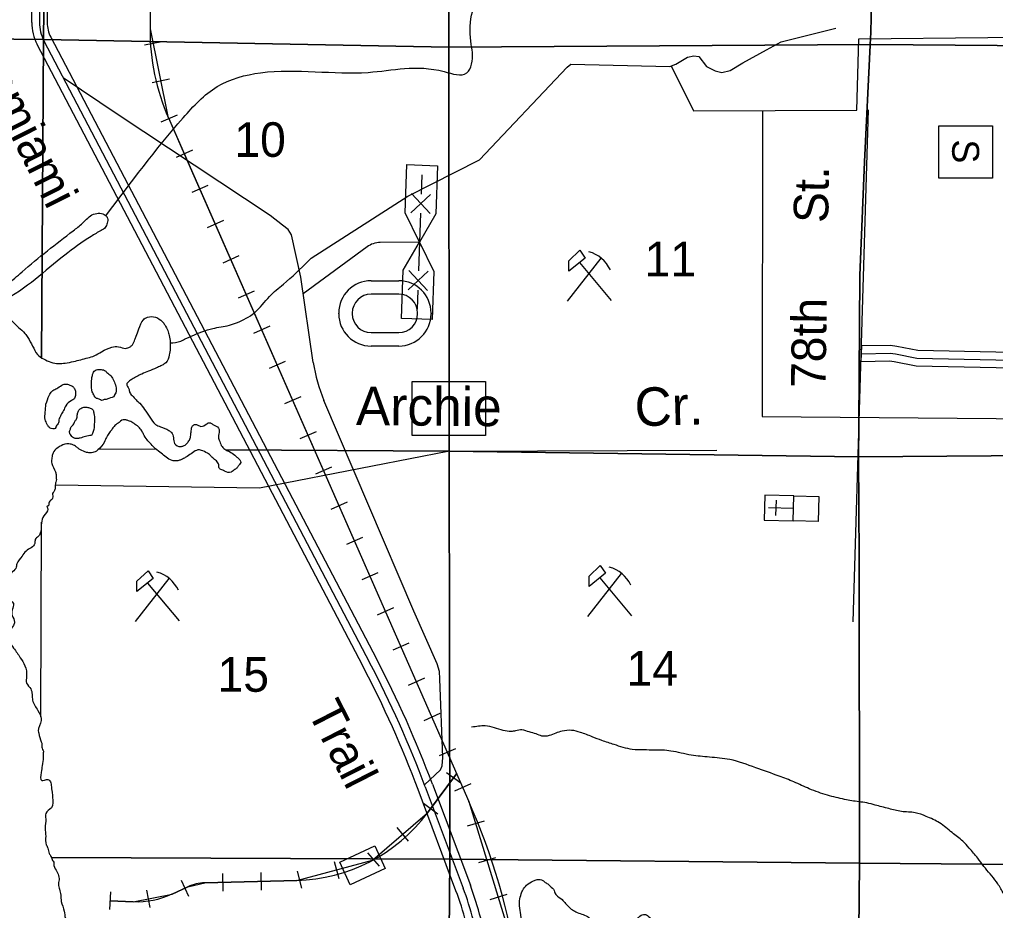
# Model space of a CAD drawing. Extents: x 380424 to 701066, y 1117407 to 1412949.
# Drawn here: x 526006 to 538699, y 1282967 to 1294552 of the extents above; entities that cross this region are included whole.
import ezdxf

# ---------------------------------------------------------------- set-up
doc = ezdxf.new("R2010")
doc.units = 0
for name, color, linetype in [('Cities Incorporated Area', 7, 'Continuous'), ('Culture', 7, 'Continuous'), ('Islands', 7, 'Continuous'), ('Lakes and Ponds Text', 7, 'Continuous'), ('Local Roads Divided Highway Outline and Fill', 7, 'Continuous'), ('Local Roads Paved', 7, 'Continuous'), ('Local Roads Related Cells', 7, 'Continuous'), ('Local Roads Related Text', 7, 'Continuous'), ('Masks for Text', 7, 'Continuous'), ('Narrow Canals', 7, 'Continuous'), ('Narrow River Creek and Branch and Slough', 7, 'Continuous'), ('Railroad Stations', 7, 'Continuous'), ('Railroads', 7, 'Continuous'), ('Section Lines', 7, 'Continuous'), ('Section Numbers', 7, 'Continuous'), ('US Highways Related Text', 7, 'Continuous'), ('US Route Divided Highway Outline and Fill', 7, 'Continuous'), ('US Routes Highway Center Lines', 7, 'Continuous'), ('Wide Rivers and Canals', 7, 'Continuous')]:
    doc.layers.add(name, color=color, linetype=linetype)

msp = doc.modelspace()

# ---------------------------------------------------------------- linework, layer by layer
at = {"layer": 'Cities Incorporated Area'}
for points in [[(523814, 1294042), (523870, 1293952), (523903, 1293762), (523903, 1293715), (524050, 1293710), (524183, 1293592), (524325, 1293478), (524339, 1293379), (524358, 1293152), (524495, 1293076), (524528, 1293000), (524618, 1292877), (524656, 1292825), (524708, 1292782), (524846, 1292750), (524883, 1292670), (524957, 1292539), (525068, 1292391), (525142, 1292327), (525216, 1292196), (525247, 1292111), (525290, 1292006), (525353, 1291905), (525453, 1291810), (525553, 1291736), (525627, 1291620), (525664, 1291531), (525659, 1291404), (525627, 1291219), (525590, 1291082), (525538, 1290966), (525538, 1290929), (525574, 1290929), (525648, 1290966), (525717, 1291003), (525849, 1291103), (526039, 1291272), (526704, 1291805), (526825, 1291905), (526968, 1292021), (527052, 1292032), (527121, 1292006), (527152, 1291969), (527147, 1291905), (527121, 1291847), (527068, 1291810), (526936, 1291731), (526593, 1291488), (525775, 1290882), (525675, 1290792), (525685, 1290734), (525717, 1290713), (525749, 1290697), (525786, 1290686), (525828, 1290681), (525849, 1290676), (525896, 1290644), (525933, 1290607), (525991, 1290549), (526076, 1290470), (526113, 1290417), (526176, 1290306), (526239, 1290196), (526319, 1290138), (526414, 1290095), (526514, 1290079), (526598, 1290085), (526709, 1290106), (526894, 1290153), (526978, 1290180), (527073, 1290233), (527205, 1290291), (527295, 1290296), (527384, 1290275), (527443, 1290296), (527474, 1290322), (527506, 1290391), (527522, 1290433), (527559, 1290528), (527617, 1290649), (527669, 1290681), (527775, 1290681), (527865, 1290623), (527896, 1290581), (527933, 1290507), (527954, 1290444), (527965, 1290359), (527965, 1290275), (527954, 1290190), (527907, 1290090), (527881, 1290069), (527844, 1290048), (527786, 1290021), (527685, 1289979), (527596, 1289942), (527469, 1289874), (527427, 1289847)], [(527427, 1289847), (527400, 1289810), (527427, 1289752), (527437, 1289705), (527469, 1289663), (527522, 1289605), (527569, 1289562), (527632, 1289483), (527701, 1289383), (527775, 1289288), (527838, 1289256), (527949, 1289209), (527981, 1289182), (528007, 1289114), (528023, 1289040), (528102, 1288998), (528123, 1289003), (528139, 1289008), (528176, 1289035), (528208, 1289072), (528229, 1289119), (528234, 1289172), (528239, 1289204), (528255, 1289267), (528292, 1289288), (528324, 1289277), (528366, 1289262), (528440, 1289293), (528482, 1289309), (528493, 1289304), (528530, 1289283), (528593, 1289240), (528603, 1289204), (528593, 1289124), (528609, 1289066), (528640, 1288998), (528688, 1288955), (528735, 1288934), (528804, 1288887), (528841, 1288855), (528883, 1288792), (528867, 1288766), (528857, 1288755), (528830, 1288718), (528815, 1288707), (528772, 1288676), (528757, 1288665), (528672, 1288681), (528625, 1288702), (528598, 1288729), (528598, 1288755), (528593, 1288776), (528556, 1288824), (528508, 1288861), (528477, 1288897), (528450, 1288913), (528371, 1288950), (528324, 1288955), (528255, 1288919), (528187, 1288871), (528150, 1288850), (528097, 1288824), (528055, 1288813), (528018, 1288813), (527991, 1288818), (527912, 1288861), (527849, 1288913), (527775, 1288971), (527717, 1289029), (527664, 1289087), (527617, 1289161), (527596, 1289204), (527495, 1289298), (527437, 1289330), (527406, 1289341), (527390, 1289346), (527369, 1289346), (527353, 1289346), (527321, 1289330), (527316, 1289325), (527258, 1289283), (527237, 1289262), (527205, 1289219), (527136, 1289119), (527110, 1289061), (527026, 1288955), (527005, 1288940), (526941, 1288919), (526878, 1288924), (526836, 1288940), (526767, 1288977), (526735, 1289003), (526677, 1289029), (526619, 1289035), (526524, 1288998), (526450, 1288934), (526435, 1288897)], [(526435, 1288897), (526424, 1288839), (526424, 1288781), (526473, 1288671), (526481, 1288625), (526481, 1288598), (526485, 1288571), (526477, 1288537), (526473, 1288514), (526469, 1288483), (526469, 1288449), (526450, 1288411), (526436, 1288391), (526436, 1288376), (526429, 1288316), (526391, 1288278), (526376, 1288226), (526361, 1288218), (526369, 1288204), (526339, 1288122), (526294, 1288031), (526249, 1287829), (526211, 1287791), (526204, 1287738), (526091, 1287641), (526038, 1287573), (525971, 1287476), (525956, 1287415), (525902, 1287357), (525881, 1287304), (525858, 1287251), (525843, 1287244), (525888, 1287139), (525851, 1287041), (525926, 1286958), (525911, 1286876), (525911, 1286801), (525941, 1286718), (525926, 1286673), (525844, 1286539), (525928, 1286380), (526016, 1286254), (526076, 1286149), (526098, 1286013), (526098, 1285923), (526151, 1285848), (526176, 1285700), (526245, 1285568), (526287, 1285436), (526249, 1285301), (526256, 1285271), (526287, 1285161), (526294, 1285143), (526298, 1285092), (526306, 1285060), (526316, 1285038), (526314, 1285018), (526313, 1285000), (526313, 1284960), (526301, 1284850), (526286, 1284760), (526294, 1284655), (526376, 1284670), (526414, 1284625), (526421, 1284557), (526429, 1284512), (526436, 1284437), (526421, 1284302), (526346, 1284227), (526346, 1284159), (526339, 1284039), (526346, 1283934), (526354, 1283821), (526376, 1283776), (526391, 1283708), (526414, 1283671), (526436, 1283618), (526451, 1283595), (526451, 1283573), (526481, 1283490), (526519, 1283348), (526511, 1283310), (526526, 1283242), (526541, 1283167), (526549, 1283085), (526587, 1282957), (526602, 1282867), (526632, 1282792), (526656, 1282702), (526688, 1282591), (526714, 1282539), (526762, 1282401), (526799, 1282333), (526878, 1282217), (526941, 1282159), (527084, 1282021), (527115, 1281937)]]:
    msp.add_spline(points, degree=3, dxfattribs=at)
at = {"layer": 'Culture'}
for p, q in [((533132, 1290890), (533569, 1291450)), ((533288, 1291391), (533702, 1290899)), ((530578, 1291156), (530938, 1291156)), ((530938, 1290981), (530578, 1290981)), ((530158, 1290726), (530158, 1290736)), ((530333, 1290736), (530333, 1290726)), ((531183, 1290726), (531183, 1290736)), ((531358, 1290736), (531358, 1290726)), ((530578, 1290481), (530938, 1290481)), ((530938, 1290306), (530578, 1290306)), ((535701, 1288368), (535692, 1288043)), ((536075, 1288358), (535701, 1288368)), ((535843, 1288102), (535849, 1288302)), ((536066, 1288033), (536075, 1288358)), ((536071, 1288195), (535746, 1288204)), ((535692, 1288043), (536066, 1288033)), ((527514, 1286724), (527951, 1287284)), ((533396, 1286790), (533834, 1287350)), ((533553, 1287291), (533966, 1286799)), ((527671, 1287225), (528084, 1286732))]:
    msp.add_line(p, q, dxfattribs=at)
for points in [[(538661, 1293169), (538661, 1292491), (537961, 1292491), (537961, 1293169)], [(533294, 1291551), (533364, 1291451), (533149, 1291279), (533149, 1291414)], [(536066, 1288033), (536075, 1288358), (536400, 1288349), (536391, 1288024)], [(527677, 1287385), (527746, 1287285), (527531, 1287113), (527531, 1287248)], [(533559, 1287451), (533628, 1287351), (533413, 1287179), (533413, 1287314)]]:
    msp.add_lwpolyline(points, close=True, dxfattribs=at)
for centre, radius, start, end in [((533298, 1291117), 431, 24.5415, 74.8304), ((530578, 1290736), 420, 90.0005, 180.0005), ((530938, 1290736), 420, 0.0005, 90.0005), ((530578, 1290736), 245, 90.0005, 180.0005), ((530938, 1290736), 245, 0.0005, 90.0005), ((530578, 1290726), 420, 180.0005, 270.0005), ((530578, 1290726), 245, 180.0005, 270.0005), ((530938, 1290726), 420, 270.0005, 0.0005), ((530938, 1290726), 245, 270.0005, 0.0005), ((533563, 1287017), 431, 24.5415, 74.8304), ((527680, 1286951), 431, 24.5415, 74.8304)]:
    msp.add_arc(centre, radius, start, end, dxfattribs=at)
at = {"layer": 'Islands'}
for points in [[(527216, 1289890), (527168, 1289942), (527142, 1289963), (527110, 1289990), (527052, 1290000), (526989, 1289990), (526957, 1289937), (526946, 1289884), (526941, 1289837), (526941, 1289773), (526952, 1289710), (526978, 1289657), (526999, 1289631), (527041, 1289615), (527073, 1289599), (527105, 1289610), (527121, 1289610), (527168, 1289626), (527237, 1289657), (527242, 1289673), (527258, 1289700), (527263, 1289742), (527216, 1289890)], [(526350, 1289552), (526340, 1289446), (526340, 1289351), (526366, 1289288), (526377, 1289267), (526419, 1289235), (526477, 1289246), (526477, 1289251), (526509, 1289298), (526519, 1289346), (526545, 1289409), (526577, 1289467), (526609, 1289531), (526677, 1289594), (526720, 1289626), (526730, 1289652), (526735, 1289700), (526725, 1289742), (526698, 1289779), (526672, 1289795), (526630, 1289810), (526572, 1289805), (526503, 1289763), (526450, 1289736), (526429, 1289721), (526392, 1289663), (526350, 1289552)], [(526941, 1289145), (526978, 1289246), (526978, 1289293), (526983, 1289372), (526978, 1289409), (526973, 1289425), (526962, 1289473), (526925, 1289499), (526883, 1289510), (526841, 1289510), (526793, 1289488), (526767, 1289452), (526757, 1289409), (526746, 1289357), (526725, 1289325), (526704, 1289283), (526672, 1289246), (526667, 1289225), (526656, 1289193), (526667, 1289156), (526709, 1289114), (526751, 1289103), (526793, 1289109), (526862, 1289130), (526941, 1289145)]]:
    msp.add_spline(points, degree=3, dxfattribs=at)
at = {"layer": 'Local Roads Divided Highway Outline and Fill'}
msp.add_lwpolyline([(541837, 1290665), (541439, 1290756), (541052, 1290646), (540160, 1290374), (539516, 1290210), (537688, 1290248), (537416, 1290302), (537335, 1290315), (536956, 1290307), (536950, 1290107), (537321, 1290115), (537381, 1290105), (537667, 1290049), (539539, 1290009), (540214, 1290181), (541108, 1290454), (541445, 1290550), (541719, 1290487), (541995, 1290106), (542081, 1289725), (542276, 1289769), (542181, 1290191)], close=True, dxfattribs=at)
at = {"layer": 'Local Roads Paved'}
for p, q in [((530527, 1291595), (529695, 1290987)), ((531208, 1291658), (530697, 1291652))]:
    msp.add_line(p, q, dxfattribs=at)
for points in [[(529827, 1290091), (529663, 1291201), (529545, 1291752), (529501, 1291820), (529425, 1291880), (529266, 1292003), (527290, 1293312), (526575, 1293795)], [(536848, 1286720), (537049, 1293379)], [(536953, 1290207), (537328, 1290215), (537399, 1290203), (537677, 1290148), (539527, 1290109), (540187, 1290278), (541080, 1290550), (541442, 1290653), (541778, 1290576), (542088, 1290149), (542179, 1289747)], [(531273, 1284599), (531479, 1284795), (531504, 1284848), (531511, 1284957), (531472, 1285981), (531469, 1286073), (531437, 1286174), (531133, 1286861), (529965, 1289599)]]:
    msp.add_lwpolyline(points, dxfattribs=at)
for centre, radius, start, end in [((530700, 1291358), 294, 90.7258, 126.1803), ((531801, 1290382), 1996, 188.3772, 203.1025)]:
    msp.add_arc(centre, radius, start, end, dxfattribs=at)
at = {"layer": 'Local Roads Related Cells'}
for p, q in [((531021, 1292040), (531044, 1292665)), ((531044, 1292665), (531444, 1292651)), ((531444, 1292651), (531421, 1292026)), ((531239, 1292533), (531230, 1292283)), ((531353, 1292279), (531094, 1292038)), ((531346, 1292029), (531105, 1292288)), ((531208, 1291658), (531021, 1292040)), ((531221, 1292033), (531194, 1291284)), ((531421, 1292026), (531208, 1291658)), ((530994, 1291291), (531208, 1291658)), ((531208, 1291658), (531394, 1291276)), ((530972, 1290666), (530994, 1291291)), ((531319, 1291279), (531060, 1291038)), ((531310, 1291029), (531069, 1291288)), ((531394, 1291276), (531371, 1290652)), ((531185, 1291034), (531176, 1290784)), ((531371, 1290652), (530972, 1290666))]:
    msp.add_line(p, q, dxfattribs=at)
at = {"layer": 'Masks for Text'}
msp.add_lwpolyline([(531113, 1289845), (532067, 1289845), (532067, 1289143), (531113, 1289143)], close=True, dxfattribs=at)
at = {"layer": 'Narrow Canals'}
for points in [[(534481, 1293949), (534771, 1293365), (536895, 1293374), (536922, 1294303), (540279, 1294335), (540379, 1296837), (541350, 1296969), (541841, 1297264), (541587, 1297776), (541624, 1298236), (542984, 1298241)], [(529801, 1291448), (531058, 1292255), (531987, 1292727), (533128, 1293934), (533177, 1293971), (534464, 1293943), (534541, 1293971), (534695, 1294061), (534776, 1294079), (534839, 1294070), (534939, 1293943), (535052, 1293885), (535142, 1293862), (535250, 1293889), (535413, 1293989), (535720, 1294160), (535910, 1294260), (536623, 1294440)], [(535671, 1293369), (535665, 1289389), (540231, 1289352), (540257, 1292340), (543646, 1292308)], [(526472, 1288501), (529125, 1288461), (531578, 1288939), (535075, 1288952)]]:
    msp.add_lwpolyline(points, dxfattribs=at)
for points in [[(527129, 1291999), (528134, 1293274), (528577, 1293680), (529142, 1293860), (530540, 1293865), (531527, 1293876), (531823, 1293860), (531886, 1293971), (531875, 1294271), (531896, 1294653), (532027, 1294972), (532278, 1295386), (532404, 1295454), (533027, 1295575), (537022, 1295523)], [(529765, 1291414), (529783, 1291431), (529801, 1291448)], [(528450, 1290516), (528519, 1290535), (528735, 1290577), (528841, 1290614), (528952, 1290667), (529062, 1290740), (529258, 1290952), (529437, 1291110), (529765, 1291414)], [(527965, 1290347), (528102, 1290371), (528170, 1290403), (528450, 1290516)]]:
    msp.add_spline(points, degree=3, dxfattribs=at)
at = {"layer": 'Narrow River Creek and Branch and Slough'}
msp.add_spline([(540059, 1281312), (539978, 1281541), (539962, 1281567), (539941, 1281636), (539925, 1281688), (539899, 1281773), (539893, 1281852), (539856, 1281937), (539782, 1282021), (539719, 1282074), (539645, 1282121), (539598, 1282164), (539518, 1282274), (539482, 1282332), (539402, 1282438), (539323, 1282528), (539260, 1282586), (539154, 1282676), (539075, 1282755), (539007, 1282860), (538890, 1283034), (538785, 1283219), (538711, 1283341), (538547, 1283541), (538468, 1283647), (538357, 1283779), (538273, 1283868), (538136, 1283979), (537972, 1284106), (537798, 1284190), (537655, 1284238), (537476, 1284254), (537312, 1284291), (537133, 1284338), (537027, 1284365), (536922, 1284380), (536737, 1284412), (536515, 1284465), (536278, 1284549), (536077, 1284639), (535887, 1284713), (535581, 1284824), (535243, 1284929), (534979, 1284961), (534742, 1284987), (534478, 1285040), (534367, 1285051), (534256, 1285051), (534130, 1285056), (533976, 1285061), (533739, 1285125), (533581, 1285177), (533454, 1285225), (533301, 1285283), (533185, 1285309), (533063, 1285299), (532979, 1285272), (532894, 1285241), (532799, 1285235), (532726, 1285262), (532636, 1285288), (532541, 1285315), (532456, 1285304), (532398, 1285293), (532298, 1285309), (532182, 1285341), (532060, 1285367), (531976, 1285362), (531886, 1285351)], degree=3, dxfattribs=at)
at = {"layer": 'Railroad Stations'}
msp.add_lwpolyline([(530171, 1283597), (530625, 1283806), (530761, 1283511), (530306, 1283302)], close=True, dxfattribs=at)
at = {"layer": 'Railroads'}
for p, q in [((527855, 1294264), (527630, 1294219)), ((527955, 1293775), (527730, 1293729)), ((528054, 1293310), (527843, 1293217)), ((527945, 1293272), (531851, 1284383)), ((528255, 1292852), (528044, 1292760)), ((528456, 1292394), (528245, 1292302)), ((528657, 1291937), (528446, 1291844)), ((528858, 1291479), (528648, 1291386)), ((529059, 1291021), (528849, 1290929)), ((529260, 1290563), (529050, 1290471)), ((529462, 1290106), (529251, 1290013)), ((529663, 1289648), (529452, 1289555)), ((529864, 1289190), (529653, 1289098)), ((530065, 1288732), (529854, 1288640)), ((530266, 1288275), (530056, 1288182)), ((530467, 1287817), (530257, 1287724)), ((530668, 1287359), (530458, 1287267)), ((530870, 1286901), (530659, 1286809)), ((531071, 1286444), (530860, 1286351)), ((531272, 1285986), (531061, 1285893)), ((531473, 1285528), (531263, 1285435)), ((531674, 1285070), (531464, 1284978)), ((531691, 1284745), (531311, 1284237)), ((531561, 1284763), (531745, 1284626)), ((531875, 1284613), (531665, 1284520)), ((531262, 1284363), (531446, 1284225)), ((532049, 1284130), (531829, 1284063)), ((530911, 1284044), (531062, 1283870)), ((530533, 1283717), (530683, 1283543)), ((530099, 1283606), (530158, 1283384)), ((532196, 1283652), (531976, 1283585)), ((528644, 1283447), (528650, 1283218)), ((529143, 1283460), (529149, 1283230)), ((529615, 1283478), (529675, 1283255)), ((528108, 1283362), (528204, 1283153)), ((529611, 1283357), (528416, 1283327)), ((527188, 1283209), (527178, 1282979)), ((527657, 1283233), (527701, 1283007)), ((528196, 1283276), (527990, 1283181)), ((527483, 1283081), (527183, 1283094)), ((532342, 1283174), (532123, 1283107))]:
    msp.add_line(p, q, dxfattribs=at)
for points in [[(527818, 1316822), (527769, 1314966), (527704, 1294432)], [(527717, 1298738), (527704, 1294432), (527936, 1293291), (527945, 1293272), (528149, 1292806)], [(528149, 1292806), (530563, 1287313)], [(530563, 1287313), (531851, 1284383), (532458, 1282405), (532495, 1282194), (532572, 1281683)], [(527183, 1283094), (527483, 1283081), (527483, 1283081), (527990, 1283181), (527990, 1283181), (528196, 1283276), (528196, 1283276), (528416, 1283327), (528416, 1283327), (529611, 1283357), (529611, 1283357), (530596, 1283620), (531311, 1284237), (531311, 1284237), (531691, 1284745)]]:
    msp.add_lwpolyline(points, dxfattribs=at)
for centre, radius, start, end in [((530558, 1294420), 2855, 179.7639, 203.7218), ((523660, 1280784), 8947, 9.0714, 23.7218), ((529554, 1285550), 2194, 271.4789, 323.2199), ((528430, 1282764), 563, 91.4788, 114.624), ((527529, 1284187), 1106, 267.6146, 294.6239)]:
    msp.add_arc(centre, radius, start, end, dxfattribs=at)
at = {"layer": 'Section Lines'}
msp.add_line((526287, 1288015), (526277, 1285479), dxfattribs=at)
for points in [[(519496, 1299615), (526380, 1299609), (526318, 1294291), (523621, 1294324)], [(523621, 1294324), (526318, 1294291), (526290, 1290153)], [(526290, 1290153), (526318, 1294291), (531589, 1294194), (531592, 1288939), (528686, 1288957)], [(528686, 1288957), (531592, 1288939), (531603, 1283636), (526420, 1283657)], [(527786, 1288962), (527037, 1288967)], [(526420, 1283657), (531603, 1283636), (531554, 1278291), (530277, 1278295)]]:
    msp.add_lwpolyline(points, dxfattribs=at)
for points in [[(531586, 1299511), (531589, 1294194), (526318, 1294291), (526380, 1299609)], [(537084, 1299501), (537086, 1299490), (537088, 1297845), (537092, 1294985), (537080, 1294384), (537070, 1294229), (531589, 1294194), (531586, 1299511)], [(542312, 1299491), (542312, 1299480), (542298, 1297086), (542295, 1294219), (539266, 1294209), (537082, 1294229), (537070, 1294229), (537080, 1294384), (537092, 1294985), (537088, 1297845), (537086, 1299490), (537084, 1299501), (539444, 1299487), (542305, 1299491)], [(537070, 1294229), (537070, 1294219), (536994, 1292700), (536933, 1291223), (536922, 1289281), (536918, 1288867), (531592, 1288939), (531589, 1294194)], [(542295, 1294219), (542295, 1294211), (542297, 1291485), (542279, 1288918), (542262, 1288918), (539792, 1288887), (536918, 1288867), (536922, 1289281), (536933, 1291223), (536994, 1292700), (537070, 1294219), (537070, 1294229), (537082, 1294229), (539266, 1294209)], [(536918, 1288867), (536927, 1287548), (536930, 1283582), (531603, 1283636), (531592, 1288939)], [(542279, 1288918), (542261, 1287549), (542237, 1283539), (536930, 1283582), (536927, 1287548), (536918, 1288867), (539792, 1288887), (542262, 1288918)], [(536930, 1283582), (536877, 1278265), (531554, 1278291), (531603, 1283636)], [(542237, 1283539), (542182, 1278243), (536877, 1278265), (536930, 1283582)]]:
    msp.add_lwpolyline(points, close=True, dxfattribs=at)
at = {"layer": 'US Route Divided Highway Outline and Fill'}
for p, q in [((526412, 1294322), (530647, 1286240)), ((530470, 1286147), (526235, 1294229)), ((531377, 1284609), (531870, 1283294)), ((531682, 1283224), (531190, 1284538))]:
    msp.add_line(p, q, dxfattribs=at)
for points in [[(526166, 1294514), (526214, 1301788), (526423, 1320900)], [(526623, 1320898), (526414, 1301787), (526366, 1294513)]]:
    msp.add_lwpolyline(points, dxfattribs=at)
for centre, radius, start, end in [((526771, 1294510), 605, 179.6203, 207.6532), ((526771, 1294510), 405, 179.6203, 207.6532), ((517860, 1279540), 14436, 20.5561, 27.6532), ((517860, 1279540), 14236, 20.5561, 27.6532), ((527770, 1281757), 4178, 8.8172, 20.5561), ((527770, 1281757), 4378, 8.8172, 20.5561)]:
    msp.add_arc(centre, radius, start, end, dxfattribs=at)
at = {"layer": 'US Routes Highway Center Lines'}
for p, q in [((526324, 1294275), (530558, 1286193)), ((531283, 1284573), (531776, 1283259))]:
    msp.add_line(p, q, dxfattribs=at)
msp.add_lwpolyline([(526523, 1320899), (526314, 1301788), (526266, 1294513)], dxfattribs=at)
for centre, radius, start, end in [((526771, 1294510), 505, 179.6203, 207.6532), ((517860, 1279540), 14336, 20.5561, 27.6532), ((527770, 1281757), 4278, 8.8172, 20.5561)]:
    msp.add_arc(centre, radius, start, end, dxfattribs=at)
at = {"layer": 'Wide Rivers and Canals'}
msp.add_spline([(532263, 1282010), (532315, 1282028), (532362, 1282071), (532442, 1282092), (532463, 1282097), (532521, 1282118), (532568, 1282166), (532595, 1282250), (532600, 1282345), (532595, 1282466), (532595, 1282556), (532584, 1282625), (532542, 1282757), (532526, 1282910), (532510, 1283026), (532510, 1283094), (532531, 1283184), (532552, 1283232), (532600, 1283295), (532690, 1283353), (532737, 1283369), (532779, 1283369), (532811, 1283358), (532843, 1283332), (532885, 1283306), (532906, 1283284), (532959, 1283226), (532969, 1283195), (533048, 1283121), (533143, 1283021), (533259, 1282941), (533407, 1282878), (533476, 1282804), (533608, 1282736), (533713, 1282646), (533787, 1282551), (533845, 1282408), (533898, 1282303), (533930, 1282182), (533935, 1282150), (533972, 1282108), (533977, 1282102), (533982, 1282129), (533982, 1282155), (533982, 1282187), (533977, 1282287), (533982, 1282366), (533972, 1282451), (533967, 1282583), (533993, 1282725), (534030, 1282841), (534093, 1282904), (534146, 1282915), (534199, 1282878), (534204, 1282873), (534188, 1282667), (534178, 1282445), (534165, 1281951), (533958, 1281862), (533844, 1281684), (533735, 1281651), (533773, 1281579), (534119, 1281613), (534360, 1281642), (534410, 1281680), (534447, 1281712), (534457, 1281733), (534468, 1281854), (534463, 1282081), (534468, 1282182), (534465, 1282310), (534459, 1282458), (534463, 1282572), (534489, 1282656), (534531, 1282672), (534558, 1282662), (534589, 1282625), (534605, 1282572), (534605, 1282514), (534595, 1282445), (534595, 1282345), (534587, 1282278), (534587, 1282198), (534683, 1282176), (534763, 1282168), (534793, 1282168), (534844, 1282139), (534888, 1282117), (534939, 1282102), (535042, 1282102), (535289, 1282101)], degree=3, dxfattribs=at)

# ---------------------------------------------------------------- texts
at = {"layer": 'Culture'}
msp.add_text('S', height=350, rotation=270.0005, dxfattribs=at).set_placement((538136, 1292994))
at = {"layer": 'Lakes and Ponds Text'}
for s, rotation, p in [('Archie', 359.5573, (530380, 1289278)), ('Cr.', 1.6959, (534013, 1289262))]:
    msp.add_text(s, height=500, rotation=rotation, dxfattribs=at).set_placement(p)
at = {"layer": 'Local Roads Related Text'}
for s, p in [('St.', (536523, 1291904)), ('78th', (536488, 1289758))]:
    msp.add_text(s, height=450, rotation=89.1233, dxfattribs=at).set_placement(p)
at = {"layer": 'Section Numbers'}
for s, p in [('10', (528800, 1292766)), ('11', (534136, 1291213)), ('15', (528581, 1285811)), ('14', (533900, 1285891))]:
    msp.add_text(s, height=450, dxfattribs=at).set_placement(p)
at = {"layer": 'US Highways Related Text'}
for s, rotation, p in [('Tamiami', 296.6915, (525341, 1294124)), ('Trail', 297.0505, (529744, 1285556))]:
    msp.add_text(s, height=450, rotation=rotation, dxfattribs=at).set_placement(p)

doc.saveas('drawing.dxf')
